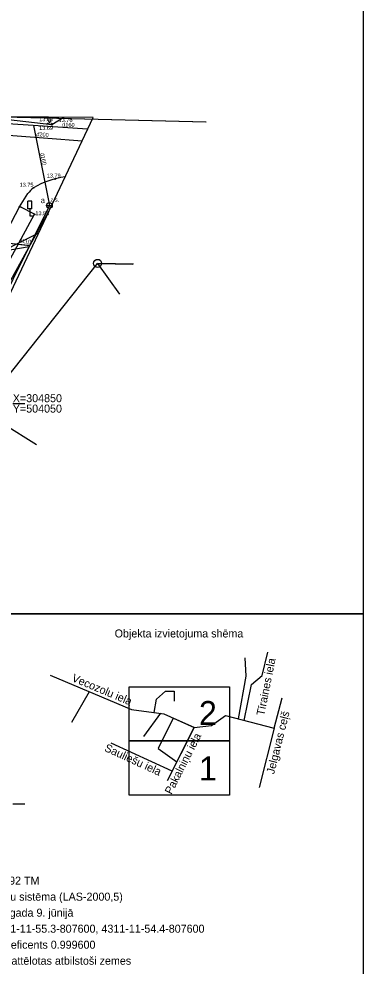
# Model space of a CAD drawing. Extents: x 503904 to 504094, y 304688 to 304960.
# Drawn here: x 504050.8 to 504093.7, y 304779.7 to 304898 of the extents above; entities that cross this region are included whole.
import ezdxf

# ---------------------------------------------------------------- set-up
doc = ezdxf.new("R2010")
doc.units = 0
for name, color, linetype in [('APGR_ELEM_####_####_#', 7, 'Continuous'), ('APGR_SARK_####_####_#', 7, 'Continuous'), ('APGS_ACRL_####_####_#', 7, 'Continuous'), ('APGS_ACRL_####_TKST_#', 7, 'Continuous'), ('APGS_VADP_ZSPR_####_#', 7, 'Continuous'), ('CELI_CAPM_####_####_#', 7, 'Continuous'), ('CELI_CMAL_####_####_#', 7, 'Continuous'), ('CELI_CSEG_####_TKST_#', 7, 'Continuous'), ('CELI_ELEM_####_####_#', 7, 'Continuous'), ('GAZE_VADP_VSP2_####_#', 7, 'Continuous'), ('GEOD_ELEM_####_####_#', 7, 'Continuous'), ('GEOD_KORD_####_TKST_#', 7, 'Continuous'), ('NORB_ZOGS_KOKA_####_#', 7, 'Continuous'), ('RAMI_PLAN_####_TKST_#', 7, 'Continuous'), ('RAMI_UZMR_####_####_#', 7, 'Continuous'), ('RELJ_AATZ_####_TKST_#', 7, 'Continuous'), ('RELJ_ELEM_####_####_#', 7, 'Continuous'), ('ROBZ_UZMR_####_####_#', 7, 'Continuous'), ('SKAN_VADP_PAST_####_I', 7, 'Continuous'), ('SKAN_VADP_PAST_TKST_I', 7, 'Continuous'), ('TERT_ELEM_####_####_#', 7, 'Continuous'), ('UDTK_ELEM_####_####_#', 7, 'Continuous'), ('UDTK_ELEM_####_TKST_#', 7, 'Continuous'), ('UDTK_VADP_NEDR_####_#', 7, 'Continuous'), ('UDTK_VADP_UDEN_####_#', 7, 'Continuous'), ('UDTK_VADP_UDEN_TKST_#', 7, 'Continuous')]:
    doc.layers.add(name, color=color, linetype=linetype)

msp = doc.modelspace()

# ---------------------------------------------------------------- linework, layer by layer
at = {"layer": 'APGR_ELEM_####_####_#'}
msp.add_circle((504060.58, 304867.49), 0.5, dxfattribs=at)
at = {"layer": 'APGR_SARK_####_####_#'}
for p, q in [((504048.87, 304885.77), (504074.07, 304885.17)), ((504046.12, 304849.29), (504060.58, 304867.49)), ((504060.58, 304867.49), (504064.99, 304867.38))]:
    msp.add_line(p, q, dxfattribs=at)
at = {"layer": 'APGS_ACRL_####_####_#'}
msp.add_lwpolyline([(504038.42, 304876.08), (504038.24, 304875.67), (504038.23, 304875.56), (504038.28, 304875.45), (504038.33, 304875.34), (504049.18, 304870.06), (504052.14, 304869.73)], dxfattribs=at)
at = {"layer": 'APGS_VADP_ZSPR_####_#'}
msp.add_lwpolyline([(504006.08, 304886.02), (504006.52, 304886.46), (504007.48, 304887.87), (504008.45, 304889.28), (504008.62, 304889.41), (504008.82, 304889.39), (504016.17, 304885.87), (504023.51, 304882.35), (504029.46, 304879.53), (504035.49, 304876.68), (504037.94, 304875.53), (504038.21, 304875.63), (504038.42, 304876.08), (504038.23, 304875.56), (504038.33, 304875.34), (504039.64, 304874.71), (504041.8, 304873.67), (504045.91, 304871.66), (504049.18, 304870.06), (504051.51, 304869.8), (504052.14, 304869.74)], dxfattribs=at)
at = {"layer": 'CELI_CAPM_####_####_#'}
msp.add_lwpolyline([(504050.85, 304874.54), (504051.86, 304876.2)], dxfattribs=at)
for centre, radius, start, end in [((504058.11, 304867.26), 11.14, 98.1737, 119.738), ((504055.73, 304873.08), 4.97, 129.2268, 141.1648)]:
    msp.add_arc(centre, radius, start, end, dxfattribs=at)
at = {"layer": 'CELI_CMAL_####_####_#'}
for points in [[(504056.37, 304885.72), (504054.86, 304884.79), (504047.25, 304885.66), (504038.18, 304887.54), (504028.06, 304891.48), (504020.04, 304895.21), (504011.33, 304899.02)], [(504032.16, 304840.29), (504039.53, 304853.7), (504045.71, 304864.82), (504050.85, 304874.54)], [(504032.56, 304836.77), (504041.26, 304852.59), (504047.43, 304863.92), (504052.72, 304873.61), (504051.01, 304874.52), (504050.88, 304874.6)], [(504054.62, 304874.25), (504048.61, 304863.3), (504042.44, 304852.02), (504033.54, 304835.7)]]:
    msp.add_lwpolyline(points, dxfattribs=at)
at = {"layer": 'CELI_ELEM_####_####_#'}
for p, q in [((504052.39, 304875.26), (504051.89, 304875.26)), ((504051.89, 304874.29), (504051.89, 304875.26)), ((504052.39, 304874.29), (504051.89, 304874.29)), ((504052.14, 304874.29), (504052.14, 304873.41)), ((504052.39, 304874.29), (504052.39, 304875.26)), ((504052.14, 304873.41), (504052.46, 304873.41))]:
    msp.add_line(p, q, dxfattribs=at)
at = {"layer": 'GAZE_VADP_VSP2_####_#'}
msp.add_lwpolyline([(503989.7, 304903.41), (504000, 304898.04), (504010.21, 304892.71), (504011.05, 304889.41), (504011.88, 304886.12), (504025.3, 304879.49), (504038.71, 304872.86), (504042.75, 304870.73), (504047.16, 304868.74), (504052.06, 304869.59)], dxfattribs=at)
at = {"layer": 'GEOD_ELEM_####_####_#'}
for p, q in [((504050, 304850), (504051.5, 304850)), ((504050, 304800), (504051.5, 304800))]:
    msp.add_line(p, q, dxfattribs=at)
at = {"layer": 'NORB_ZOGS_KOKA_####_#'}
msp.add_lwpolyline([(504052.99, 304885.74), (504055.53, 304885.64), (504055.75, 304885.73)], dxfattribs=at)
at = {"layer": 'RAMI_PLAN_####_TKST_#'}
for p, q in [((504059.54, 304814), (504057.34, 304810.15)), ((504068.45, 304811.3), (504066.32, 304808.39)), ((504072.62, 304809.51), (504069.27, 304802.88)), ((504082.61, 304809.44), (504080.76, 304802.03)), ((504069.87, 304804.08), (504062.29, 304807.56))]:
    msp.add_line(p, q, dxfattribs=at)
for points in [[(503904.2, 304959.85), (504093.7, 304959.85), (504093.7, 304823.74), (503904.2, 304823.74)], [(503904.2, 304823.74), (504093.7, 304823.74), (504093.7, 304687.63), (503904.2, 304687.63)], [(504064.51, 304814.62), (504077.04, 304814.62), (504077.04, 304807.86), (504064.51, 304807.86)], [(504070, 304810.71), (504068.12, 304806.92), (504070.47, 304805.25), (504072.62, 304809.51)], [(504064.51, 304807.86), (504077.04, 304807.86), (504077.04, 304801.09), (504064.51, 304801.09)]]:
    msp.add_lwpolyline(points, close=True, dxfattribs=at)
for points in [[(504078.88, 304810.42), (504079.77, 304814.89), (504081.12, 304816.03), (504081.84, 304818.95)], [(504078.16, 304810.61), (504079.12, 304815.94), (504079.01, 304818.22)], [(504054.65, 304816.05), (504064.81, 304811.79), (504068.85, 304811.24), (504072.62, 304809.51), (504074.78, 304809.79), (504076.56, 304811.03), (504082.61, 304809.44), (504083.61, 304813.24)], [(504067.65, 304811.4), (504067.92, 304813.07), (504069.07, 304814.06), (504070.15, 304814.06), (504070.15, 304812.8)]]:
    msp.add_lwpolyline(points, dxfattribs=at)
at = {"layer": 'RAMI_UZMR_####_####_#'}
msp.add_lwpolyline([(503923.25, 304801.02), (503981.98, 304759.67), (503995.48, 304748.81), (504027.75, 304817.25), (504060.02, 304885.7), (504048.87, 304885.77), (504036.8, 304888.85), (503994.54, 304908.3), (503981.12, 304894.75), (503978.52, 304892.44), (503950.89, 304846.73), (503923.25, 304801.02)], dxfattribs=at)
at = {"layer": 'RELJ_ELEM_####_####_#'}
for centre in [(504053.1, 304885.74), (504055.53, 304885.64), (504054.86, 304884.79), (504055.28, 304878.03), (504052.59, 304876.93), (504050.85, 304874.54), (504052.72, 304873.61)]:
    msp.add_circle(centre, 0.05, dxfattribs=at)
at = {"layer": 'ROBZ_UZMR_####_####_#'}
for points in [[(503976.96, 304916.7), (503989.76, 304910.58), (503994.54, 304908.3), (504011.53, 304900.19), (504020.19, 304896.05), (504036.8, 304888.85), (504048.87, 304885.77), (504074.12, 304885.17)], [(504052.95, 304844.81), (504048.85, 304847.4), (504030.46, 304860.12), (503981.12, 304894.75), (503968.01, 304904.03)], [(504065.05, 304867.38), (504060.58, 304867.49), (504063.3, 304863.64)]]:
    msp.add_lwpolyline(points, dxfattribs=at)
at = {"layer": 'SKAN_VADP_PAST_####_I'}
msp.add_lwpolyline([(504023.78, 304835.98), (504032.73, 304853.58), (504047.21, 304883.67), (504054.39, 304883.11), (504058.65, 304882.79)], dxfattribs=at)
at = {"layer": 'TERT_ELEM_####_####_#'}
for p, q in [((504054.35, 304885.48), (504054.6, 304884.98)), ((504054.6, 304884.98), (504054.85, 304885.48))]:
    msp.add_line(p, q, dxfattribs=at)
for centre, radius in [((504054.35, 304884.98), 0.028), ((504054.85, 304884.98), 0.0263)]:
    msp.add_circle(centre, radius, dxfattribs=at)
at = {"layer": 'UDTK_ELEM_####_####_#'}
msp.add_line((504054.22, 304874.71), (504054.92, 304874.71), dxfattribs=at)
msp.add_circle((504054.57, 304874.71), 0.351, dxfattribs=at)
at = {"layer": 'UDTK_VADP_NEDR_####_#'}
msp.add_lwpolyline([(504018.29, 304854.81), (504025.16, 304857.88), (504029.29, 304859.73), (504035.8, 304862.53), (504046.5, 304867.92), (504053.24, 304871.32)], dxfattribs=at)
at = {"layer": 'UDTK_VADP_UDEN_####_#'}
for points in [[(504059.33, 304884.23), (504052.53, 304884.69), (504043.03, 304885.34), (504032.96, 304889.37), (504014.27, 304897.49), (504000, 304903.85), (503993.13, 304906.88)], [(504052.6, 304884.69), (504054.56, 304874.71), (504047.68, 304860.84), (504037.41, 304840.14), (504031.39, 304828), (504014.79, 304793.58), (504000, 304762.91), (503998.94, 304760.72), (503997.89, 304758.53), (503994.03, 304750.1), (503993.99, 304750.01)]]:
    msp.add_lwpolyline(points, dxfattribs=at)

# ---------------------------------------------------------------- texts
at = {"layer": 'APGS_ACRL_####_TKST_#'}
msp.add_text('d110', height=0.5, rotation=353.7374, dxfattribs=at).set_placement((504050.74, 304870.08))
at = {"layer": 'CELI_CSEG_####_TKST_#'}
msp.add_text('a', height=0.7, dxfattribs=at).set_placement((504053.49, 304875.01))
at = {"layer": 'GEOD_KORD_####_TKST_#'}
for s, p in [('X=304850', (504050, 304850.15)), ('Y=504050', (504050, 304848.85))]:
    msp.add_text(s, height=1, dxfattribs=at).set_placement(p)
at = {"layer": 'RAMI_PLAN_####_TKST_#'}
for s, height, p in [('Objekta izvietojuma shēma', 1, (504062.71, 304820.77)), ('2', 3, (504073.23, 304809.83)), ('1', 3, (504073.23, 304802.91))]:
    msp.add_text(s, height=height, dxfattribs=at).set_placement(p)
for s, rotation, p in [('Tīraines iela', 78.7392, (504081.37, 304810.94)), ('Vecozolu iela', 337.237, (504057.28, 304815.34)), ('Jelgavas ceļš', 75.971, (504082.6, 304803.64)), ('Pakalniņu iela', 63.1592, (504069.8, 304801.09)), ('Sauliešu iela', 335.3788, (504061.35, 304806.63)), ('1.  Koordinātu sistēma: LKS92 TM', 360, (504032.96, 304789.9)), ('2. Latvijas normālo augstumu sistēma (LAS-2000,5)', 360, (504032.96, 304787.9)), ('3. Uzmērīšana veikta 2016. gada 9. jūnijā', 360, (504032.96, 304785.9)), ('4. Kartes lapas TKS 93: 4311-11-55.3-807600, 4311-11-54.4-807600', 360, (504032.96, 304783.9)), ('5. TM projekcijas mēroga koeficents 0.999600', 360, (504032.96, 304781.9)), ('6. Zemes vienību robežas ir attēlotas atbilstoši zemes ', 360, (504032.96, 304779.9))]:
    msp.add_text(s, height=1, rotation=rotation, dxfattribs=at).set_placement(p)
at = {"layer": 'RELJ_AATZ_####_TKST_#'}
for s, p in [(' 13.80', (504053.1, 304885.24)), (' 13.76', (504055.53, 304885.14)), (' 13.69', (504053.09, 304884.15)), (' 13.79', (504054.05, 304878.2)), (' 13.75', (504050.66, 304877.05)), (' 13.83', (504052.63, 304873.5))]:
    msp.add_text(s, height=0.5, dxfattribs=at).set_placement(p)
at = {"layer": 'SKAN_VADP_PAST_TKST_I'}
msp.add_text('d200', height=0.5, rotation=355.5995, dxfattribs=at).set_placement((504052.93, 304883.38))
at = {"layer": 'UDTK_ELEM_####_TKST_#'}
msp.add_text('z.s.', height=0.5, dxfattribs=at).set_placement((504054.71, 304875.2))
at = {"layer": 'UDTK_VADP_UDEN_TKST_#'}
for rotation, p in [(356.1, (504056.16, 304884.6)), (281.1343, (504053.43, 304881.24))]:
    msp.add_text('d160', height=0.5, rotation=rotation, dxfattribs=at).set_placement(p)

doc.saveas('drawing.dxf')
